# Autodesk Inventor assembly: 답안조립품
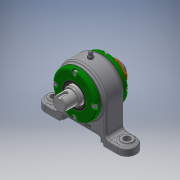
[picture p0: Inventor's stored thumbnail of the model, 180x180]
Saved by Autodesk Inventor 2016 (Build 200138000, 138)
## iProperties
Created: 2019-05
Part Number: 답안조립품
Material: 일반
Document SubType Name: Assembly
Designer: USER
Author: USER
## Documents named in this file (13)
- C:\Users\USER\Desktop\490504V1027\답안조립품.iam
- C:\Users\USER\Desktop\490504V1027\본체.ipt
- C:\Users\USER\Desktop\490504V1027\축.ipt
- C:\Users\USER\Desktop\490504V1027\칼라.ipt
- C:\Users\USER\Desktop\490504V1027\커버.ipt
- C:\Users\USER\Desktop\490504V1027\개스킷.ipt
- C:\Users\USER\Desktop\490504V1027\그리스니플 M6.ipt
- 그리스니플  M6.ipt
- C:\Users\USER\Desktop\490504V1027\그리스니플개스킷.ipt
- C:\Users\USER\Desktop\490504V1027\베어링너트.ipt
- C:\Users\USER\Desktop\490504V1027\볼트 M4.ipt
- C:\Users\USER\Desktop\490504V1027\앵귤러 볼 베어링 7205.ipt
- C:\Users\USER\Desktop\490504V1027\오일 실 28 40 5 B.ipt
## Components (4 placed, 3 different names)
1. 개스킷:1
2. 그리스니플  M6:1
3. 그리스니플개스킷:1
4. 개스킷:2
